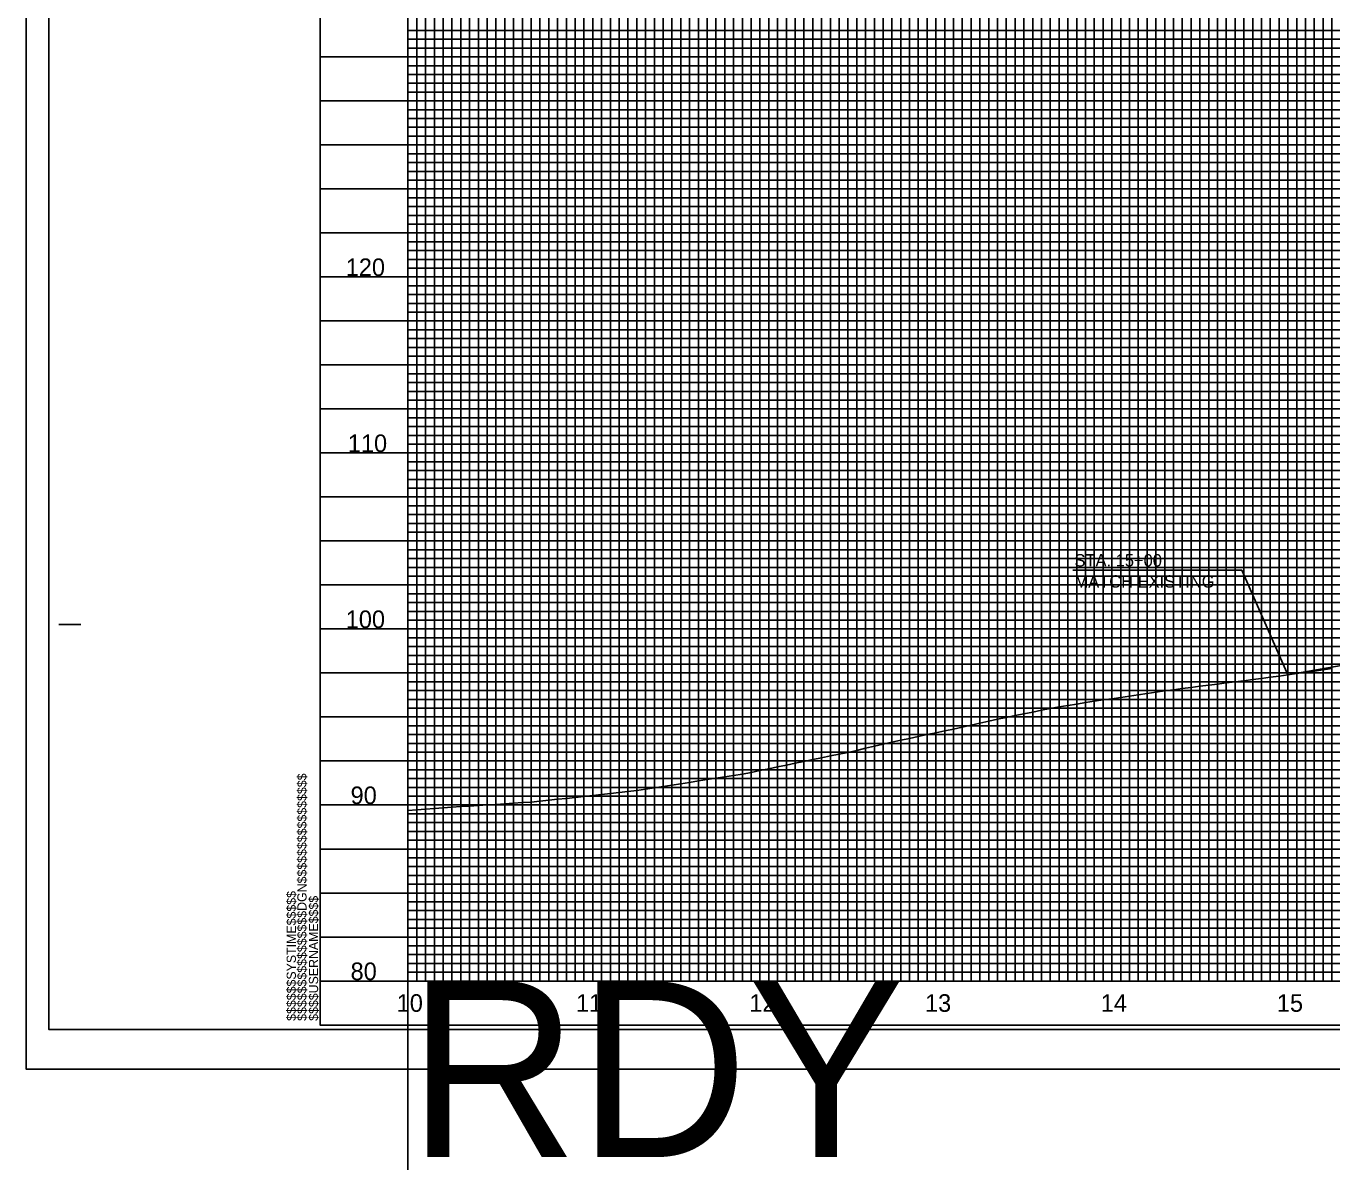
# Model space of a CAD drawing. Extents: x 2345490 to 2436403, y 465165 to 573888.
# Drawn here: x 2381550 to 2382292, y 500505 to 501150 of the extents above; entities that cross this region are included whole.
import ezdxf

# ---------------------------------------------------------------- set-up
doc = ezdxf.new("R2010")
doc.units = 0
for name, color, linetype in [('Exist Vertical Profile Horizontal Axis Label Major', 7, 'Continuous'), ('Exist Vertical Profile Vertical Axis Label', 7, 'Continuous'), ('Old_Level_1', 7, 'Continuous'), ('Old_Level_18', 7, 'Continuous'), ('Old_Level_2', 7, 'Continuous'), ('Old_Level_40', 7, 'Continuous'), ('Old_Level_41', 7, 'Continuous'), ('Old_Level_42', 7, 'Continuous'), ('Old_Level_43', 7, 'Continuous'), ('Old_Level_50', 7, 'Continuous'), ('Old_Level_51', 7, 'Continuous'), ('Old_Level_52', 7, 'Continuous'), ('Old_Level_57', 7, 'Continuous'), ('Old_Level_63', 7, 'Continuous')]:
    doc.layers.add(name, color=color, linetype=linetype)

msp = doc.modelspace()

# ---------------------------------------------------------------- linework, layer by layer
at = {"layer": 'Old_Level_1'}
for points in [[(2382266.7988, 500781.7756), (2382271.7988, 500782.49286), (2382276.7988, 500783.21002), (2382281.7988, 500783.87219), (2382286.7988, 500784.53371), (2382291.7988, 500785.26166)], [(2381766.7988, 500704.60955), (2381771.7988, 500705.02857), (2381776.7988, 500705.4476), (2381781.7988, 500705.86622), (2381786.7988, 500706.19256), (2381791.7988, 500706.51891), (2381796.7988, 500706.84525), (2381801.7988, 500707.1716), (2381806.7988, 500707.49795), (2381811.7988, 500707.82429), (2381816.7988, 500708.15054), (2381821.7988, 500708.4768), (2381826.7988, 500708.80305), (2381831.7988, 500709.1293), (2381836.7988, 500709.45556), (2381841.7988, 500709.92663), (2381846.7988, 500710.46117), (2381851.7988, 500710.99572), (2381856.7988, 500711.53026), (2381861.7988, 500712.06481), (2381866.7988, 500712.59973), (2381871.7988, 500713.19984), (2381876.7988, 500713.74575), (2381881.7988, 500714.29247), (2381886.7988, 500714.83998), (2381891.7988, 500715.38826), (2381896.7988, 500715.96902), (2381901.7988, 500716.71153), (2381906.7988, 500717.48115), (2381911.7988, 500718.25175), (2381916.7988, 500719.02333), (2381921.7988, 500719.79587), (2381926.7988, 500720.59725), (2381931.7988, 500721.42203), (2381936.7988, 500722.19354), (2381941.7988, 500722.96437), (2381946.7988, 500723.73449), (2381951.7988, 500724.50388), (2381956.7988, 500725.27727), (2381961.7988, 500726.26238), (2381966.7988, 500727.30666), (2381971.7988, 500728.35126), (2381976.7988, 500729.39616), (2381981.7988, 500730.44133), (2381986.7988, 500731.49), (2381991.7988, 500732.56213), (2381996.7988, 500733.59983), (2382001.7988, 500734.63614), (2382006.7988, 500735.67104), (2382011.7988, 500736.61079), (2382016.7988, 500737.60077), (2382021.7988, 500738.80133), (2382026.7988, 500739.98481), (2382031.7988, 500741.15117), (2382036.7988, 500742.30039), (2382041.7988, 500743.43244), (2382046.7988, 500744.54589), (2382051.7988, 500745.64296), (2382056.7988, 500746.72259), (2382061.7988, 500747.78475), (2382066.7988, 500748.8294), (2382071.7988, 500749.85653), (2382076.7988, 500750.87428), (2382081.7988, 500752.02714), (2382086.7988, 500753.16146), (2382091.7988, 500754.27721), (2382096.7988, 500755.37435), (2382101.7988, 500756.45287), (2382106.7988, 500757.51472), (2382111.7988, 500758.55573), (2382116.7988, 500759.57831), (2382121.7988, 500760.58242), (2382126.7988, 500761.56805), (2382131.7988, 500762.53516), (2382136.7988, 500763.46147), (2382141.7988, 500764.34223), (2382146.7988, 500765.14112), (2382151.7988, 500765.91826), (2382156.7988, 500766.69014), (2382161.7988, 500767.45673), (2382166.7988, 500768.18216), (2382171.7988, 500768.93589), (2382176.7988, 500769.68607), (2382181.7988, 500770.43267), (2382186.7988, 500771.17569), (2382191.7988, 500771.91511), (2382196.7988, 500772.57238), (2382201.7988, 500773.23503), (2382206.7988, 500773.89505), (2382211.7988, 500774.55243), (2382216.7988, 500775.20715), (2382221.7988, 500775.8592), (2382226.7988, 500776.46346), (2382231.7988, 500777.10984), (2382236.7988, 500777.7545), (2382241.7988, 500778.39743), (2382246.7988, 500779.03862), (2382251.7988, 500779.66595), (2382256.7988, 500780.34087), (2382261.7988, 500781.05827), (2382266.7988, 500781.7756)]]:
    msp.add_lwpolyline(points, dxfattribs=at)
at = {"layer": 'Old_Level_18'}
msp.add_line((2381716.79875, 500582.775), (2381716.79875, 500582.775), dxfattribs=at)
msp.add_line((2381716.79875, 500582.775), (2381716.79875, 500582.775), dxfattribs=at)
msp.add_lwpolyline([(2383216.79875, 501632.775), (2381716.79875, 501632.775), (2381716.79875, 500582.775), (2383216.79875, 500582.775)], close=True, dxfattribs=at)
at = {"layer": 'Old_Level_2'}
for p, q in [((2382144.62525, 500841.2375), (2382240.66125, 500841.2375)), ((2382266.799, 500781.77575), (2382240.66125, 500841.2375)), ((2382266.799, 500781.77575), (2382305.849, 500788.57525))]:
    msp.add_line(p, q, dxfattribs=at)
at = {"layer": 'Old_Level_40'}
msp.add_line((2381716.79875, 500582.775), (2381716.79875, 500582.775), dxfattribs=at)
msp.add_line((2381716.79875, 500582.775), (2381716.79875, 500582.775), dxfattribs=at)
msp.add_line((2381716.79875, 500582.775), (2381716.79875, 500582.775), dxfattribs=at)
msp.add_line((2381716.79875, 500582.775), (2381716.79875, 500582.775), dxfattribs=at)
at = {"layer": 'Old_Level_41'}
for p, q in [((2381568.29875, 500810.275), (2381580.79875, 500810.275)), ((2383216.79875, 500607.775), (2381716.79875, 500607.775))]:
    msp.add_line(p, q, dxfattribs=at)
for points in [[(2381716.79875, 501632.775), (2381766.79875, 501632.775), (2381766.79875, 500607.775), (2381816.79875, 500607.775), (2381816.79875, 501632.775), (2381866.79875, 501632.775), (2381866.79875, 500607.775), (2381916.79875, 500607.775), (2381916.79875, 501632.775), (2381966.79875, 501632.775), (2381966.79875, 500607.775), (2382016.79875, 500607.775), (2382016.79875, 501632.775), (2382066.79875, 501632.775), (2382066.79875, 500607.775), (2382116.79875, 500607.775), (2382116.79875, 501632.775), (2382166.79875, 501632.775), (2382166.79875, 500607.775), (2382216.79875, 500607.775), (2382216.79875, 501632.775), (2382266.79875, 501632.775), (2382266.79875, 500607.775), (2382316.79875, 500607.775)], [(2381791.79875, 500607.775), (2381791.79875, 501632.775), (2381841.79875, 501632.775), (2381841.79875, 500607.775), (2381891.79875, 500607.775), (2381891.79875, 501632.775), (2381941.79875, 501632.775), (2381941.79875, 500607.775), (2381991.79875, 500607.775), (2381991.79875, 501632.775), (2382041.79875, 501632.775), (2382041.79875, 500607.775), (2382091.79875, 500607.775), (2382091.79875, 501632.775), (2382141.79875, 501632.775), (2382141.79875, 500607.775), (2382191.79875, 500607.775), (2382191.79875, 501632.775), (2382241.79875, 501632.775), (2382241.79875, 500607.775), (2382291.79875, 500607.775), (2382291.79875, 501632.775), (2382341.79875, 501632.775)], [(2383216.79875, 501132.775), (2381716.79875, 501132.775), (2381716.79875, 501082.775), (2383216.79875, 501082.775)], [(2383216.79875, 501032.775), (2381716.79875, 501032.775), (2381716.79875, 500982.775), (2383216.79875, 500982.775)], [(2383216.79875, 500957.775), (2381716.79875, 500957.775), (2381716.79875, 501007.775), (2383216.79875, 501007.775)], [(2383216.79875, 500932.775), (2381716.79875, 500932.775), (2381716.79875, 500882.775), (2383216.79875, 500882.775)], [(2383216.79875, 500857.775), (2381716.79875, 500857.775), (2381716.79875, 500907.775), (2383216.79875, 500907.775)], [(2383216.79875, 500832.775), (2381716.79875, 500832.775), (2381716.79875, 500782.775), (2383216.79875, 500782.775)], [(2383216.79875, 500732.775), (2381716.79875, 500732.775), (2381716.79875, 500682.775), (2383216.79875, 500682.775)], [(2383216.79875, 500657.775), (2381716.79875, 500657.775), (2381716.79875, 500707.775), (2383216.79875, 500707.775)], [(2383216.79875, 500632.775), (2381716.79875, 500632.775)], [(2381754.29875, 500582.775), (2381754.29875, 500582.775)]]:
    msp.add_lwpolyline(points, dxfattribs=at)
at = {"layer": 'Old_Level_42'}
for points in [[(2383216.79875, 501057.775), (2381716.79875, 501057.775), (2381716.79875, 501107.775), (2383216.79875, 501107.775)], [(2383216.79875, 500757.775), (2381716.79875, 500757.775), (2381716.79875, 500807.775), (2383216.79875, 500807.775)]]:
    msp.add_lwpolyline(points, dxfattribs=at)
at = {"layer": 'Old_Level_43'}
for points in [[(2381771.79875, 501632.775), (2381771.79875, 500607.775), (2381776.79875, 500607.775), (2381776.79875, 501632.775)], [(2381781.79875, 501632.775), (2381781.79875, 500607.775), (2381786.79875, 500607.775), (2381786.79875, 501632.775)], [(2381796.79875, 501632.775), (2381796.79875, 500607.775), (2381801.79875, 500607.775), (2381801.79875, 501632.775)], [(2381806.79875, 501632.775), (2381806.79875, 500607.775), (2381811.79875, 500607.775), (2381811.79875, 501632.775)], [(2381821.79875, 501632.775), (2381821.79875, 500607.775), (2381826.79875, 500607.775), (2381826.79875, 501632.775)], [(2381831.79875, 501632.775), (2381831.79875, 500607.775), (2381836.79875, 500607.775), (2381836.79875, 501632.775)], [(2381846.79875, 501632.775), (2381846.79875, 500607.775), (2381851.79875, 500607.775), (2381851.79875, 501632.775)], [(2381856.79875, 501632.775), (2381856.79875, 500607.775), (2381861.79875, 500607.775), (2381861.79875, 501632.775)], [(2381871.79875, 501632.775), (2381871.79875, 500607.775), (2381876.79875, 500607.775), (2381876.79875, 501632.775)], [(2381881.79875, 501632.775), (2381881.79875, 500607.775), (2381886.79875, 500607.775), (2381886.79875, 501632.775)], [(2381896.79875, 501632.775), (2381896.79875, 500607.775), (2381901.79875, 500607.775), (2381901.79875, 501632.775)], [(2381906.79875, 501632.775), (2381906.79875, 500607.775), (2381911.79875, 500607.775), (2381911.79875, 501632.775)], [(2381921.79875, 501632.775), (2381921.79875, 500607.775), (2381926.79875, 500607.775), (2381926.79875, 501632.775)], [(2381931.79875, 500607.775), (2381936.79875, 500607.775), (2381936.79875, 501632.775)], [(2381931.79875, 501632.775), (2381931.79875, 500607.775)], [(2381946.79875, 501632.775), (2381946.79875, 500607.775), (2381951.79875, 500607.775), (2381951.79875, 501632.775)], [(2381956.79875, 501632.775), (2381956.79875, 500607.775), (2381961.79875, 500607.775), (2381961.79875, 501632.775)], [(2381971.79875, 501632.775), (2381971.79875, 500607.775), (2381976.79875, 500607.775), (2381976.79875, 501632.775)], [(2381981.79875, 501632.775), (2381981.79875, 500607.775), (2381986.79875, 500607.775), (2381986.79875, 501632.775)], [(2381996.79875, 501632.775), (2381996.79875, 500607.775), (2382001.79875, 500607.775), (2382001.79875, 501632.775)], [(2382006.79875, 501632.775), (2382006.79875, 500607.775), (2382011.79875, 500607.775), (2382011.79875, 501632.775)], [(2382021.79875, 501632.775), (2382021.79875, 500607.775), (2382026.79875, 500607.775), (2382026.79875, 501632.775)], [(2382031.79875, 501632.775), (2382031.79875, 500607.775), (2382036.79875, 500607.775), (2382036.79875, 501632.775)], [(2382046.79875, 501632.775), (2382046.79875, 500607.775), (2382051.79875, 500607.775), (2382051.79875, 501632.775)], [(2382056.79875, 501632.775), (2382056.79875, 500607.775), (2382061.79875, 500607.775), (2382061.79875, 501632.775)], [(2382071.79875, 501632.775), (2382071.79875, 500607.775), (2382076.79875, 500607.775), (2382076.79875, 501632.775)], [(2382081.79875, 501632.775), (2382081.79875, 500607.775), (2382086.79875, 500607.775), (2382086.79875, 501632.775)], [(2382096.79875, 501632.775), (2382096.79875, 500607.775), (2382111.79875, 500607.775), (2382111.79875, 501632.775)], [(2382101.79875, 501632.775), (2382101.79875, 500607.775), (2382106.79875, 500607.775), (2382106.79875, 501632.775)], [(2382101.79875, 501632.175), (2382101.79875, 500607.775), (2382106.79875, 500607.775), (2382106.79875, 501632.175)], [(2382121.79875, 501632.775), (2382121.79875, 500607.775), (2382126.79875, 500607.775), (2382126.79875, 501632.775)], [(2382131.79875, 501632.775), (2382131.79875, 500607.775), (2382136.79875, 500607.775), (2382136.79875, 501632.775)], [(2382146.79875, 501632.775), (2382146.79875, 500607.775), (2382151.79875, 500607.775), (2382151.79875, 501632.775)], [(2382156.79875, 501632.775), (2382156.79875, 500607.775), (2382161.79875, 500607.775), (2382161.79875, 501632.775)], [(2382171.79875, 501632.775), (2382171.79875, 500607.775), (2382176.79875, 500607.775), (2382176.79875, 501632.775)], [(2382181.79875, 501632.775), (2382181.79875, 500607.775), (2382186.79875, 500607.775), (2382186.79875, 501632.775)], [(2382196.79875, 501632.775), (2382196.79875, 500607.775), (2382201.79875, 500607.775), (2382201.79875, 501632.775)], [(2382206.79875, 501632.775), (2382206.79875, 500607.775), (2382211.79875, 500607.775), (2382211.79875, 501632.775)], [(2382221.79875, 501632.775), (2382221.79875, 500607.775), (2382226.79875, 500607.775), (2382226.79875, 501632.775)], [(2382231.79875, 501632.775), (2382231.79875, 500607.775), (2382236.79875, 500607.775), (2382236.79875, 501632.775)], [(2382246.79875, 501632.775), (2382246.79875, 500607.775)], [(2382251.79875, 501632.775), (2382251.79875, 500607.775), (2382256.79875, 500607.775), (2382256.79875, 501632.775), (2382261.79875, 501632.775), (2382261.79875, 500607.775), (2382271.79875, 500607.775), (2382271.79875, 501632.775), (2382276.79875, 501632.775), (2382276.79875, 500607.775), (2382281.79875, 500607.775), (2382281.79875, 501632.775), (2382286.79875, 501632.775), (2382286.79875, 500607.775)], [(2383166.79875, 501147.775), (2381766.79875, 501147.775), (2381766.79875, 501142.775), (2383166.79875, 501142.775)], [(2383166.79875, 501137.775), (2381766.79875, 501137.775), (2381766.79875, 501127.775), (2383166.79875, 501127.775)], [(2383166.79875, 501122.775), (2381766.79875, 501122.775), (2381766.79875, 501117.775), (2383166.79875, 501117.775)], [(2383166.79875, 501112.775), (2381766.79875, 501112.775)], [(2381766.79875, 501102.775), (2383166.79875, 501102.775)], [(2383166.79875, 501097.775), (2381766.79875, 501097.775), (2381766.79875, 501092.775), (2383166.79875, 501092.775)], [(2383166.79875, 501087.775), (2381766.79875, 501087.775), (2381766.79875, 501077.775), (2383166.79875, 501077.775)], [(2383166.79875, 501072.775), (2381766.79875, 501072.775), (2381766.79875, 501067.775), (2383166.79875, 501067.775)], [(2383166.79875, 501062.775), (2381766.79875, 501062.775), (2381766.79875, 501052.775), (2383166.79875, 501052.775)], [(2383166.79875, 501047.775), (2381766.79875, 501047.775), (2381766.79875, 501042.775), (2383166.79875, 501042.775)], [(2383166.79875, 501037.775), (2381766.79875, 501037.775), (2381766.79875, 501027.775), (2383166.79875, 501027.775)], [(2383166.79875, 501022.775), (2381766.79875, 501022.775), (2381766.79875, 501017.775), (2383166.79875, 501017.775)], [(2383166.79875, 501012.775), (2381766.79875, 501012.775), (2381766.79875, 501002.775), (2383166.79875, 501002.775)], [(2383166.79875, 500997.775), (2381766.79875, 500997.775), (2381766.79875, 500992.775), (2383166.79875, 500992.775)], [(2383166.79875, 500987.775), (2381766.79875, 500987.775), (2381766.79875, 500977.775), (2383166.79875, 500977.775)], [(2383166.79875, 500972.775), (2381766.79875, 500972.775), (2381766.79875, 500967.775), (2383166.79875, 500967.775)], [(2383166.79875, 500962.775), (2381766.79875, 500962.775), (2381766.79875, 500952.775), (2383166.79875, 500952.775)], [(2383166.79875, 500947.775), (2381766.79875, 500947.775), (2381766.79875, 500942.775), (2383166.79875, 500942.775)], [(2383166.79875, 500937.775), (2381766.79875, 500937.775), (2381766.79875, 500927.775), (2383166.79875, 500927.775)], [(2383166.79875, 500922.775), (2381766.79875, 500922.775), (2381766.79875, 500917.775), (2383166.79875, 500917.775)], [(2383166.79875, 500912.775), (2381766.79875, 500912.775), (2381766.79875, 500902.775), (2383166.79875, 500902.775)], [(2383166.79875, 500897.775), (2381766.79875, 500897.775), (2381766.79875, 500892.775), (2383166.79875, 500892.775)], [(2383166.79875, 500887.775), (2381766.79875, 500887.775), (2381766.79875, 500877.775), (2383166.79875, 500877.775)], [(2383166.79875, 500872.775), (2381766.79875, 500872.775), (2381766.79875, 500867.775), (2383166.79875, 500867.775)], [(2383166.79875, 500862.775), (2381766.79875, 500862.775), (2381766.79875, 500852.775), (2383166.79875, 500852.775)], [(2383166.79875, 500847.775), (2381766.79875, 500847.775), (2381766.79875, 500842.775), (2383166.79875, 500842.775)], [(2383166.79875, 500837.775), (2381766.79875, 500837.775), (2381766.79875, 500827.775), (2383166.79875, 500827.775)], [(2383166.79875, 500822.775), (2381766.79875, 500822.775), (2381766.79875, 500817.775), (2383166.79875, 500817.775)], [(2383166.79875, 500812.775), (2381766.79875, 500812.775)], [(2381766.79875, 500802.775), (2383166.79875, 500802.775)], [(2383166.79875, 500797.775), (2381766.79875, 500797.775), (2381766.79875, 500792.775), (2383166.79875, 500792.775)], [(2383166.79875, 500787.775), (2381766.79875, 500787.775)], [(2381766.79875, 500777.775), (2383166.79875, 500777.775)], [(2383166.79875, 500772.775), (2381766.79875, 500772.775), (2381766.79875, 500767.775), (2383166.79875, 500767.775)], [(2383166.79875, 500762.775), (2381766.79875, 500762.775), (2381766.79875, 500752.775), (2383166.79875, 500752.775)], [(2383166.79875, 500747.775), (2381766.79875, 500747.775), (2381766.79875, 500742.775), (2383166.79875, 500742.775)], [(2383166.79875, 500737.775), (2381766.79875, 500737.775), (2381766.79875, 500727.775), (2383166.79875, 500727.775)], [(2383166.79875, 500722.775), (2381766.79875, 500722.775), (2381766.79875, 500717.775), (2383166.79875, 500717.775)], [(2383166.79875, 500712.775), (2381766.79875, 500712.775), (2381766.79875, 500702.775), (2383166.79875, 500702.775)], [(2383166.79875, 500697.775), (2381766.79875, 500697.775), (2381766.79875, 500692.775), (2383166.79875, 500692.775)], [(2383166.79875, 500687.775), (2381766.79875, 500687.775), (2381766.79875, 500677.775), (2383166.79875, 500677.775)], [(2383166.79875, 500672.775), (2381766.79875, 500672.775), (2381766.79875, 500667.775), (2383166.79875, 500667.775)], [(2383166.79875, 500662.775), (2381766.79875, 500662.775), (2381766.79875, 500652.775), (2383166.79875, 500652.775)], [(2383166.79875, 500647.775), (2381766.79875, 500647.775), (2381766.79875, 500642.775), (2383166.79875, 500642.775)], [(2383166.79875, 500637.775), (2381766.79875, 500637.775), (2381766.79875, 500627.775), (2383166.79875, 500627.775)], [(2383166.79875, 500622.775), (2381766.79875, 500622.775), (2381766.79875, 500617.775), (2383166.79875, 500617.775)], [(2383166.79875, 500612.775), (2381766.79875, 500612.775)]]:
    msp.add_lwpolyline(points, dxfattribs=at)
at = {"layer": 'Old_Level_50'}
msp.add_line((2381549.79875, 500557.775), (2381549.79875, 500557.775), dxfattribs=at)
msp.add_lwpolyline([(2383229.29875, 501635.325), (2381562.79875, 501635.325), (2381562.79875, 500580.225), (2383229.29875, 500580.225)], close=True, dxfattribs=at)
at = {"layer": 'Old_Level_51'}
msp.add_lwpolyline([(2383233.79875, 501657.775), (2381549.79875, 501657.775), (2381549.79875, 500557.775), (2383233.79875, 500557.775)], close=True, dxfattribs=at)
at = {"layer": 'Old_Level_52'}
msp.add_line((2381562.79875, 500580.225), (2381562.79875, 500580.225), dxfattribs=at)
at = {"layer": 'Old_Level_57'}
for p, q in [((2381716.79925, 501057.77525), (2385066.79875, 501057.77525)), ((2381766.79875, 500607.77525), (2381766.79875, 501057.77525)), ((2381866.79875, 500607.77525), (2381866.79875, 501057.77525)), ((2381966.79875, 500607.77525), (2381966.79875, 501057.77525)), ((2382066.79875, 500607.77525), (2382066.79875, 501057.77525)), ((2382166.79875, 500607.77525), (2382166.79875, 501057.77525)), ((2382166.79875, 500607.87525), (2382166.79875, 501057.77525)), ((2382266.79875, 500607.77525), (2382266.79875, 501057.77525)), ((2382266.79875, 500607.87525), (2382266.79875, 501057.77525)), ((2381716.79925, 501007.77525), (2385066.79875, 501007.77525)), ((2381716.79925, 500957.77525), (2385066.79875, 500957.77525)), ((2381716.79925, 500907.77525), (2385066.79875, 500907.77525)), ((2381716.79925, 500857.77525), (2385066.79875, 500857.77525)), ((2381716.79925, 500807.77525), (2385066.79875, 500807.77525)), ((2381716.79925, 500757.77525), (2385066.79875, 500757.77525)), ((2381716.79925, 500707.77525), (2385066.79875, 500707.77525)), ((2381716.799, 500657.77525), (2385066.79875, 500657.77525)), ((2381716.79925, 500607.77525), (2385066.79875, 500607.77525))]:
    msp.add_line(p, q, dxfattribs=at)
at = {"layer": 'Old_Level_63'}
for q in [(2381766.79875, 503107.775), (2384797.7405, 500607.775), (2381766.79875, 498107.775)]:
    msp.add_line((2381766.79875, 500607.775), q, dxfattribs=at)

# ---------------------------------------------------------------- texts
at = {"layer": 'Exist Vertical Profile Horizontal Axis Label Major'}
for s, p in [('10', (2381760.38213, 500590.275)), ('11', (2381862.22153, 500590.275)), ('12', (2381960.77001, 500590.275)), ('13', (2382060.60486, 500590.275)), ('14', (2382160.44728, 500590.275)), ('15', (2382260.53971, 500590.275))]:
    msp.add_text(s, height=10, dxfattribs=at).set_placement(p)
at = {"layer": 'Exist Vertical Profile Vertical Axis Label'}
for s, p in [('120', (2381731.42759, 501008.275)), ('110', (2381732.62456, 500908.275)), ('100', (2381731.42759, 500808.275)), ('90', (2381734.18516, 500708.275)), ('80', (2381734.18516, 500608.275))]:
    msp.add_text(s, height=10, dxfattribs=at).set_placement(p)
at = {"layer": 'Old_Level_2'}
for s, height, p in [('STA. 15+00', 7.000001, (2382145.535, 500843.2815)), ('MATCH EXISTING', 7.0000005, (2382145.535, 500831.2815))]:
    msp.add_text(s, height=height, dxfattribs=at).set_placement(p)
at = {"layer": 'Old_Level_41'}
for s, p in [('$$$$$$$$$$$$$$$$DGN$$$$$$$$$$$$$$$$', (2381709.14875, 500585.1375)), ('$$$$$$SYSTIME$$$$$', (2381703.09875, 500585.1375)), ('$$$$USERNAME$$$$', (2381715.72375, 500585.15))]:
    msp.add_text(s, height=5.25, rotation=90, dxfattribs=at).set_placement(p)
at = {"layer": 'Old_Level_63'}
msp.add_text('RDY', height=100.000001, dxfattribs=at).set_placement((2381766.79875, 500507.775))

doc.saveas('drawing.dxf')
